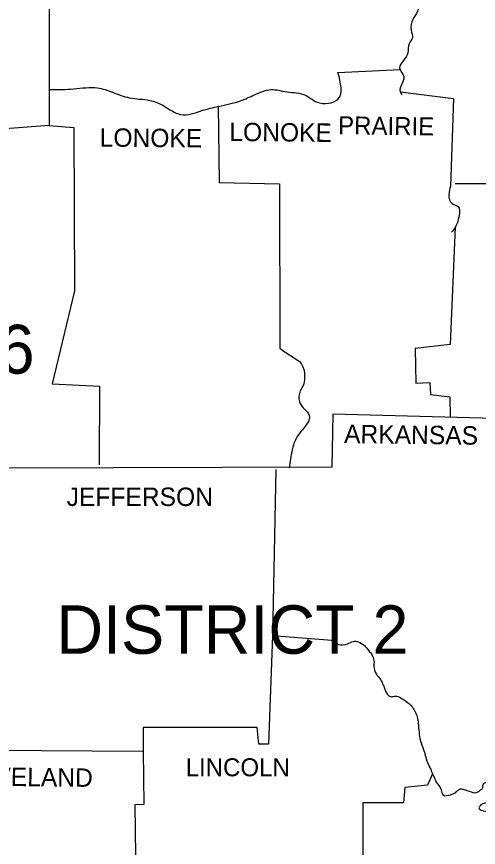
# Model space of a CAD drawing. Extents: x -33639 to 34530, y -17264 to 5867.
# Drawn here: x 2998 to 3591, y -9345 to -8278 of the extents above; entities that cross this region are included whole.
import ezdxf

# ---------------------------------------------------------------- set-up
doc = ezdxf.new("R2010")
doc.units = 0
for name, color, linetype in [('1', 7, 'Continuous'), ('2', 7, 'Continuous'), ('3', 7, 'Continuous')]:
    doc.layers.add(name, color=color, linetype=linetype)

msp = doc.modelspace()

# ---------------------------------------------------------------- linework, layer by layer
at = {"layer": '1'}
for points in [[(3003.0383899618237, -7160.749555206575), (3004.139097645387, -7291.733767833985), (2994.7830824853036, -7292.284121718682), (2996.434143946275, -7429.322226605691), (2957.909375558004, -7434.825764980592), (2961.211498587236, -7471.699471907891), (2974.4199905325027, -7488.760440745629), (2973.3192828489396, -7532.238393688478), (2898.4711613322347, -7534.990162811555), (2895.7193922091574, -7602.133330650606), (2827.4755167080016, -7604.3347459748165), (2824.1733936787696, -7685.787113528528), (2828.0258705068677, -7692.391359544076), (2829.6769320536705, -7822.27486461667), (2947.4526526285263, -7829.979818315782), (2945.801591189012, -8120.016289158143), (3039.3617430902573, -8122.768058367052), (3039.3617430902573, -8417.757713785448), (2965.614329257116, -8423.261252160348), (2960.1107909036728, -8488.203004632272), (2836.281178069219, -8488.75335851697)], [(3772.5102953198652, -8116.2340376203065), (3780.6883585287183, -8415.005944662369), (3649.704145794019, -8415.556298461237), (3649.153791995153, -8427.664082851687), (3611.179377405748, -8429.865498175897), (3607.877254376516, -8492.60583532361), (3561.647532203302, -8492.60583532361)], [(3410.850581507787, -8349.51383830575), (3490.651887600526, -8345.661361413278)], [(3490.651887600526, -8374.279760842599), (3559.446116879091, -8383.085422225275), (3555.59364007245, -8495.357604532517)], [(3256.7515077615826, -8392.441437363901), (3257.852215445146, -8490.954773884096), (3335.4521061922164, -8492.60583532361), (3336.0024599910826, -8703.941707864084)], [(3039.3617430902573, -8417.757713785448), (3071.28226546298, -8419.959129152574), (3071.832619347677, -8630.19429396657), (3043.2142199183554, -8749.621076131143), (3104.3034956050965, -8752.372845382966), (3103.7531417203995, -8853.637950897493)], [(3561.647532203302, -8548.191572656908), (3555.043286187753, -8698.98852337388), (3509.914271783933, -8703.941707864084), (3511.0149794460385, -8748.520368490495), (3529.1766559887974, -8747.97001469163), (3529.7270098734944, -8763.379922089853), (3554.492932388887, -8766.13169121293), (3555.2977983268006, -8792.692268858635)], [(3612.280085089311, -8794.199736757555), (3404.2463354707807, -8788.696198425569), (3403.1456278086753, -8856.389720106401), (2982.1249442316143, -8858.04078158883)], [(3331.0492755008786, -8859.69184315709), (3326.646444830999, -9072.678777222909), (3403.1456278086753, -9078.732669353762)], [(3326.646444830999, -9072.678777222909), (3321.693260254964, -9212.468651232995), (3309.035122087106, -9212.468651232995), (3306.833706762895, -9191.00485170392), (3160.4395867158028, -9191.00485170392), (3160.4395867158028, -9221.824666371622)], [(2964.5136215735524, -9220.173604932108), (3159.338879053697, -9221.274312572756)], [(3160.4395867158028, -9221.274312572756), (3160.9899406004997, -9290.068541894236), (3149.4325100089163, -9290.618895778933), (3152.7346330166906, -9519.015737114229)], [(3532.4787789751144, -9250.443065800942), (3525.8745329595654, -9265.302619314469), (3496.7057797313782, -9268.054388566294), (3495.0547182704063, -9287.867126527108), (3442.7711039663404, -9287.867126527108), (3442.2207500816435, -9452.42292320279)]]:
    msp.add_lwpolyline(points, dxfattribs=at)
for points in [[(3560.546824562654, -8049.570998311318), (3557.795055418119, -8067.732674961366), (3547.3383325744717, -8072.685859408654), (3535.23054820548, -8084.793643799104), (3532.4787789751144, -8095.80072050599), (3522.572409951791, -8100.203551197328), (3513.2163947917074, -8111.760981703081), (3507.162502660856, -8127.721242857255), (3507.162502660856, -8144.231857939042), (3511.0149794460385, -8162.94388834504), (3524.77382529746, -8167.897072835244), (3531.3780713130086, -8178.904149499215), (3530.277363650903, -8190.461580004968), (3543.485855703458, -8198.16653370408), (3545.687271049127, -8204.770779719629), (3543.485855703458, -8211.925379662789), (3537.4319635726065, -8232.288471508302), (3537.982317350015, -8246.047317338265), (3536.8816096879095, -8252.101209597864), (3522.0220561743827, -8255.953686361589), (3513.2163947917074, -8270.813239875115), (3507.162502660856, -8281.26996282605), (3504.961087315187, -8295.028808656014), (3506.612148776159, -8304.935177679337), (3502.209318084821, -8312.64013137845), (3500.5582566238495, -8324.197561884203), (3495.0547182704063, -8334.103930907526), (3490.101533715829, -8343.459946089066), (3495.6050720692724, -8354.467022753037), (3493.9540105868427, -8362.17197645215), (3490.651887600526, -8374.279760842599), (3493.4036567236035, -8378.13223773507)], [(3040.4624507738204, -8371.527991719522), (3071.28226546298, -8370.427284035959), (3101.551726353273, -8369.326576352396), (3120.8141106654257, -8374.830114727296), (3142.82826397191, -8381.984714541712), (3168.694894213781, -8385.286837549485), (3186.8565707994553, -8392.441437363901), (3208.3203703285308, -8403.448514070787), (3235.838062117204, -8398.495329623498), (3257.3018616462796, -8392.991791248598), (3285.369907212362, -8385.837191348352), (3303.531583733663, -8378.13223773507), (3324.4450294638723, -8371.527991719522), (3345.358475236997, -8374.279760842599), (3369.0236901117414, -8378.682591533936), (3383.8832436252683, -8387.488252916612), (3410.850581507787, -8383.635775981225), (3410.850581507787, -8349.51383830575)], [(3555.59364007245, -8495.357604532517), (3553.392224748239, -8506.364681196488), (3557.795055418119, -8517.922111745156), (3565.500009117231, -8521.774588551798), (3566.6007167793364, -8532.781665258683), (3563.8489475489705, -8543.788741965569), (3561.647532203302, -8548.191572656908), (3556.694347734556, -8554.795818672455)], [(3336.0024599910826, -8703.941707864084), (3349.761305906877, -8713.29772308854), (3364.070505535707, -8724.304799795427), (3367.922982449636, -8739.164353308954), (3366.8222747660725, -8749.621076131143), (3362.419444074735, -8758.426737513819), (3361.3187364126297, -8772.185583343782), (3367.922982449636, -8782.09195241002), (3373.9768745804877, -8790.347259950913), (3367.922982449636, -8805.206813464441), (3357.466259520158, -8818.965659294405), (3351.9627212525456, -8834.375566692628), (3348.1102443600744, -8857.490427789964)], [(3403.1456278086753, -9078.732669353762), (3411.400935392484, -9084.236207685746), (3422.9583658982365, -9083.68585380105), (3430.6633195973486, -9080.383730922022), (3436.7172117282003, -9080.934084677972), (3444.9725193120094, -9085.887269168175), (3450.476057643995, -9092.491515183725), (3454.3285344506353, -9097.444699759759), (3457.080303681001, -9105.149653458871), (3457.080303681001, -9112.304253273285), (3459.8320728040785, -9122.210622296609), (3463.134195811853, -9126.06309910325), (3467.5370265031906, -9133.217699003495), (3470.2887957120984, -9139.821945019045), (3471.9398571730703, -9144.224775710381), (3477.9937493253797, -9151.379375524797), (3483.4972877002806, -9150.829021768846), (3488.4504722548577, -9151.379375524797), (3495.0547182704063, -9155.231852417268), (3504.961087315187, -9162.93680603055), (3506.612148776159, -9165.13822135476), (3513.2163947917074, -9179.44742106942), (3514.3171024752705, -9188.253082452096), (3515.417810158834, -9199.810512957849), (3517.619225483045, -9210.817589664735), (3522.0220561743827, -9222.92537401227), (3524.223471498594, -9231.180681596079), (3529.1766559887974, -9242.738112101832), (3532.4787789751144, -9250.443065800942), (3536.8816096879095, -9260.349434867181), (3543.485855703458, -9271.356511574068), (3546.237624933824, -9277.960757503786), (3555.59364007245, -9277.410403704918), (3562.197886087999, -9274.658634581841), (3567.1510705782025, -9270.255803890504), (3573.2049628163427, -9270.80615768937), (3579.8092088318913, -9273.007573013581), (3588.614870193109, -9274.658634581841), (3594.1184084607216, -9271.356511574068), (3596.870177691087, -9269.155096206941), (3597.4205314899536, -9264.201911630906), (3602.3737160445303, -9261.450142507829), (3607.877254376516, -9265.302619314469), (3613.931146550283, -9274.108280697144), (3613.931146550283, -9279.61181902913), (3611.729731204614, -9282.91394207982), (3604.575131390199, -9287.316772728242), (3594.6687623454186, -9290.618895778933), (3591.9169931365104, -9294.471372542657), (3601.273008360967, -9298.874203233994), (3616.132561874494, -9299.974910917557), (3619.9850387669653, -9296.672787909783), (3629.8914077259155, -9299.424557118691), (3633.743884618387, -9296.672787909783), (3646.952376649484, -9297.22314179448), (3653.006268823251, -9292.820311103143), (3665.114053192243, -9293.370664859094), (3668.9665299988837, -9296.122434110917), (3668.9665299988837, -9301.075618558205), (3678.8728990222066, -9303.277033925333), (3686.027498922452, -9301.625972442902), (3695.3835140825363, -9304.377741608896), (3703.638821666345, -9308.780572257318), (3708.0416522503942, -9314.834464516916), (3713.545190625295, -9321.438710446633), (3718.498375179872, -9319.78764900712), (3722.3508519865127, -9314.834464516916), (3730.6061595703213, -9306.02880313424), (3730.6061595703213, -9300.525264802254), (3732.8075748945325, -9296.672787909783), (3735.5593440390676, -9291.169249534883)]]:
    msp.add_spline(points, degree=3, dxfattribs=at)

# ---------------------------------------------------------------- texts
at = {"layer": '2'}
for s, height, rotation, p in [('PRAIRIE', 23.114861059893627, 359.21157501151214, (3410.850581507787, -8428.76479053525)), ('LONOKE', 23.666315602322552, 359.4974194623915, (3104.3034956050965, -8444.725051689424)), ('LONOKE', 23.666315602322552, 359.4974194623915, (3271.0607074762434, -8437.570451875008)), ('ARKANSAS', 23.659711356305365, 359.2678250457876, (3418.5555351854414, -8825.569905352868)), ('CLEVELAND', 23.66631560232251, 359.33765002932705, (2907.27682271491, -9265.302619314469))]:
    msp.add_text(s, height=height, rotation=rotation, dxfattribs=at).set_placement(p)
for s, height, p in [('JEFFERSON', 23.666315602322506, (3061.926250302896, -8906.471919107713)), ('LINCOLN', 23.11486105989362, (3214.924616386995, -9253.745188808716))]:
    msp.add_text(s, height=height, dxfattribs=at).set_placement(p)
at = {"layer": '3'}
for s, height, p in [('DISTRICT 6', 62.74033716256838, (2563.856029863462, -8736.412584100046)), ('DISTRICT 2', 62.1888826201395, (3048.717758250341, -9096.343992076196))]:
    msp.add_text(s, height=height, dxfattribs=at).set_placement(p)

doc.saveas('drawing.dxf')
